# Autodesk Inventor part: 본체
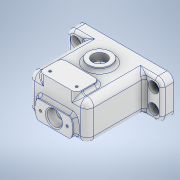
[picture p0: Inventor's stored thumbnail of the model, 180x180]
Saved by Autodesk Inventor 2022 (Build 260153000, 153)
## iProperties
Created: 2023-12
Part Number: 본체
Material: 알루미늄 6061
Document SubType Name: Modeling
Designer: PC-01
Density: 2.7 g/cm^3
Appearance: 알루미늄 - 평지
Mass: 225.061 g
Surface Area: 362.151 cm^2
Volume: 83.356 cm^3
Author: PC-01
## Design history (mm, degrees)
sketch "스케치1"
  geometry: L1 (-70, 0)-(70, 0) reference; L2 (0, -33.6)-(0, 33.6) reference; L3 (-50, 24)-(50, 24); L4 (50, 24)-(50, -24); L5 (50, -24)-(-50, -24); L6 (-50, -24)-(-50, 24); 1 further point
  constraints: 8 end point, 2 perpendicular, 1 horizontal, 2 other
  dimensions: "d0" = 100 distance of L3.start L3.end; "d1" = 48 distance of L3.end L4.end
extrude "돌출1" new body sketch "스케치1" stored distance "d2" = 76; taper "d3" = 0 deg
sketch "스케치2"
  geometry: L1 (50, -38)-(50, 38) reference; L2 (50, -26)-(31, -26); L3 (31, -26)-(31, 38); L4 (-50, 38)-(50, 38) reference; L5 (-31, 38)-(-31, -26); L6 (-31, -26)-(-50, -26); L7 (-50, -38)-(-50, 38) reference; L8 (31, 38)-(-31, 38); L9 (0, -53.2)-(0, 53.2) reference; L10 (70, 0)-(-70, 0) reference; L11 (50, -38)-(-50, -38) reference; L12 (50, -26)-(50, -38); L13 (50, -38)-(-50, -38); L14 (-50, -38)-(-50, -26); L15 (50, 38)-(50, -26); L16 (50, 38)-(31, 38); L17 (-31, 38)-(-50, 38); L18 (-50, 38)-(-50, -26); 2 further points
  constraints: 24 end point, 5 collinear, 5 perpendicular, 5 point on line, 1 vertical, 2 other
  dimensions: "d4" = 62 distance between parallel lines of L5 L3; "d5" = 12 distance between parallel lines of L11 L2
extrude "돌출2" cut sketch "스케치2" stored distance "d6" = 76; taper "d7" = 0 deg
sketch "스케치3"
  geometry: L1 (64, 0)-(0, 0) reference; L2 (76, 0)-(64, 0) reference; L3 (0, 0)-(76, 0); L4 (76, 0)-(76, 4); L5 (76, 48)-(76, 0) reference; L6 (0, 0)-(0, 48) reference; L7 (0, 0)-(0, 4); L8 (76, 4)-(0, 4); L9 (0, 48)-(64, 48) reference; L10 (0, 48)-(76, 48); L11 (76, 48)-(76, 44); L12 (76, 44)-(0, 44); L13 (0, 44)-(0, 48); 4 further points
  constraints: 16 end point, 3 point on line, 2 parallel, 2 perpendicular, 1 collinear, 1 horizontal
  dimensions: "d8" = 4 distance between parallel lines of L1 L8; "d9" = 4 distance between parallel lines of L9 L12
extrude "돌출3" cut sketch "스케치3" stored distance "d10" = 500; taper "d11" = 0 deg
sketch "스케치4" dims "d87" = 40
  geometry: L1 (19, -12)-(-81, -12) reference; L2 (19, 0)-(19, -12) reference; C1 r 20 at (-31, 16); 1 further point
  constraints: 1 centre point
  dimensions: "d12" = 40 diameter of C1; "d13" = 28 distance from line of L1 C1.centre; "d14" = 50 distance from line of L2 C1.centre
extrude "돌출4" join sketch "스케치4" distance "d15" = 4; taper "d16" = 0 deg
sketch "스케치5"
  geometry: L1 (64, 0)-(0, 0) reference; L2 (64, 40)-(0, 40) reference; L3 (0, 0)-(4, 0); L4 (4, 0)-(4, 40); L5 (4, 40)-(0, 40); L6 (0, 40)-(0, 0); 3 further points
  constraints: 8 end point, 2 parallel, 1 horizontal, 1 perpendicular, 1 point on line
  dimensions: "d17" = 4 distance between parallel lines of L6 L4
extrude "돌출5" cut sketch "스케치5" stored distance "d18" = 500; taper "d19" = 0 deg
sketch "스케치6"
  geometry: L1 (19, -72)-(81, -72) reference; L2 (70, -72)-(30, -72); L3 (30, -72)-(30, -48); L4 (30, -48)-(70, -48); L5 (70, -48)-(70, -72); L6 (19, -72)-(19, -12) reference; L7 (0, 0)-(100, 0) reference; L8 (100, 0)-(100, -12) reference; C1 r 12 at (50, -28); 2 further points
  constraints: 8 end point, 2 parallel, 1 centre point, 1 horizontal, 1 perpendicular, 1 point on line
  dimensions: "d20" = 24 distance of L4.end L2.start; "d21" = 40 distance of L3.end L4.end; "d22" = 11 distance between parallel lines of L6 L3; "d23" = 24 diameter of C1; "d24" = 28 distance from line of L7 C1.centre; "d25" = 50 distance from line of L8 C1.centre
extrude "돌출6" join sketch "스케치6" distance "d26" = 4; taper "d27" = 0 deg
sketch "스케치8"
  geometry: L1 (50, -28)-(-50, -28) reference; C1 r 9 at (0, 0); 1 further point
  constraints: 1 centre point
  dimensions: "d30" = 18 diameter of C1; "d31" = 28 distance from line of L1 C1.centre; "d32" = 10 distance of point (0, 10) C1.centre
extrude "돌출7" cut sketch "스케치8" distance "d33" = 8; taper "d34" = 0 deg
sketch "스케치10"
  geometry: C1 r 12 at (0, 0) reference; 2 further points
  constraints: 1 coincident
hole "구멍1" sketch "스케치10" at (0, 0) diameter "d35" = 14.91747; stored, may be unused: countersink angle "d39" = 90 deg, drill point angle "d41" = 0 deg; dims "d36" = 8, "d37" = 4, "d38" = 2, "d40" = 0.998
sketch "스케치12"
  geometry: L1 (27, -16)-(-27, -16); L2 (-27, -16)-(-27, 16); L3 (-27, 16)-(27, 16); L4 (27, 16)-(27, -16); L5 (70, 0)-(-70, 0) reference; L6 (0, -33.6)-(0, 33.6) reference; L7 (-50, -20)-(50, -20) reference; L8 (-31, -20)-(-31, 20) reference; 1 further point
  constraints: 8 end point, 2 parallel, 1 horizontal, 1 perpendicular, 2 other
  dimensions: "d42" = 4 distance between parallel lines of L1 L7; "d43" = 4 distance between parallel lines of L8 L2
extrude "돌출8" cut sketch "스케치12" distance "d44" = 66; taper "d45" = 0 deg
sketch "스케치13"
  geometry: L1 (50, -28)-(-50, -28) reference; L2 (50, -16)-(50, -28) reference; L3 (31, 44)-(31, -16) reference; L4 (-31, -16)-(-31, 44) reference; A1 r 15 centre (0, 0) between (0, 15) and (-15, 0); 3 further points
  constraints: 4 point on circle, 1 centre point
  dimensions: "d46" = 30 diameter of A1; "d47" = 28 distance from line of L1 A1.centre; "d48" = 50 distance from line of L2 A1.centre; "d49" = 31 distance from line of L3 A1.start; "d50" = 16 distance from line of L4 A1.end; "d51" = 16 distance from line of L3 point (15, 0); "d52" = 13 distance from line of L1 point (0, -15)
hole "구멍2" sketch "스케치13" at (0, 15), (-15, 0), (0, -15), (15, 0) diameter "d53" = 2.459; stored, may be unused: countersink angle "d57" = 90 deg, drill point angle "d59" = 0 deg; dims "d54" = 6, "d55" = 4, "d56" = 2, "d58" = 8.8
sketch "스케치14"
  geometry: L1 (30, -48)-(30, -72) reference; L2 (70, -72)-(70, -48) reference; L3 (30, -72)-(70, -72) reference; 3 further points
  dimensions: "d60" = 28 distance of point (36, -66) point (64, -66); "d61" = 6 distance from line of L1 point (36, -66); "d62" = 6 distance from line of L2 point (64, -66); "d63" = 6 distance from line of L3 point (64, -66)
hole "구멍3" sketch "스케치14" at (64, -66), (36, -66) diameter "d64" = 2.459; stored, may be unused: countersink angle "d68" = 90 deg, drill point angle "d70" = 0 deg; dims "d65" = 8, "d66" = 4, "d67" = 2, "d69" = 8
sketch "스케치15"
  geometry: L1 (100, 0)-(81, 0) reference; L2 (81, -40)-(100, -40) reference; L3 (100, 0)-(100, -40) reference; L4 (0, -40)-(0, 0) reference; 5 further points
  dimensions: "d71" = 20 distance of point (91, -10) point (91, -30); "d72" = 20 distance of point (9, -10) point (9, -30); "d73" = 82 distance of point (9, -30) point (91, -30); "d74" = 82 distance of point (9, -10) point (91, -10); "d75" = 10 distance from line of L1 point (91, -10); "d76" = 10 distance from line of L2 point (91, -30); "d77" = 9 distance from line of L3 point (91, -30); "d78" = 9 distance from line of L4 point (9, -30)
hole "구멍4" sketch "스케치15" at (91, -30), (91, -10), (9, -30), (9, -10) diameter "d79" = 6.756; stored, may be unused: countersink angle "d83" = 82 deg, drill point angle "d85" = 0 deg; dims "d80" = 8, "d81" = 11, "d82" = 6.6, "d84" = 12
sketch "스케치16"
  geometry: L1 (28, 44)-(4, 44) reference; L2 (-12, 0)-(-12, 40) reference; 2 further points
  constraints: 1 other
  dimensions: "d86" = 23 distance from line of L1 point (28, 21); "d87" = 40 distance from line of L2 point (28, 21)
feature "엠보싱1" sketch "스케치16" dims "d0" = 100, "d1" = 48, "d88" = 0.5, "d89" = 0
sketch "스케치17"
  geometry: L1 (-7.126, 23)-(-55.615, 23); L2 (-51, 44)-(-11, 44) reference; L3 (19, 40)-(19, 0) reference; L4 (0, 0)-(-62, 0) reference; L5 (-8.148, 3)-(-55.615, 3); L6 (-58, 36)-(-58, 4) reference; C1 r 20 at (-31, 13); 5 further points
  constraints: 4 end point, 1 centre point, 1 horizontal, 1 perpendicular
  dimensions: "d90" = 40 diameter of C1; "d91" = 31 distance from line of L2 C1.centre; "d92" = 50 distance from line of L3 C1.centre; "d95" = 10 distance from line of C1.centre L1; "d96" = 10 distance from line of L5 C1.centre
extrude "돌출9" join sketch "스케치17" distance "d97" = 4; taper "d98" = 0 deg
sketch "스케치18"
  geometry: L1 (-51, 44)-(-11, 44) reference; L2 (-81, 0)-(-81, 40) reference; C1 r 8 at (-31, 13); 1 further point
  constraints: 1 centre point
  dimensions: "d99" = 16 diameter of C1; "d100" = 31 distance from line of L1 C1.centre; "d101" = 50 distance from line of L2 C1.centre
extrude "돌출10" cut sketch "스케치18" distance "d102" = 20; taper "d103" = 0 deg
sketch "스케치19"
  geometry: L1 (19, 40)-(19, 0) reference; L2 (-81, 0)-(-81, 40) reference; L3 (-51, 44)-(-11, 44) reference; 3 further points
  dimensions: "d104" = 28 distance of point (-45, 13) point (-17, 13); "d105" = 36 distance from line of point (-17, 13) L1; "d106" = 36 distance from line of L2 point (-45, 13); "d107" = 31 distance from line of L3 point (-45, 13)
hole "구멍5" sketch "스케치19" at (-17, 13), (-45, 13) diameter "d108" = 2.459; stored, may be unused: countersink angle "d112" = 90 deg, drill point angle "d114" = 0 deg; dims "d109" = 10, "d110" = 4, "d111" = 2, "d113" = 8
fillet "모깎기1" dims "d115" = 7
fillet "모깎기2" dims "d116" = 7
chamfer "모따기1" distance "d117" = 1; stored, may be unused: second distance "d118" = 2, angle "d119" = 45 deg
fillet "모깎기3" dims "d120" = 5
fillet "모깎기4" dims "d121" = 7
fillet "모깎기5" dims "d122" = 3
fillet "모깎기6" dims "d123" = 3
fillet "모깎기7" dims "d124" = 3
sketch "스케치20"
  geometry: 1 further point
node "솔리드1"
feature "A9D066F2-1C7D-4E18-AEED-F7BC21143FA4" dims "d64" = 2.459, "d65" = 8, "d66" = 4, "d67" = 2, "d68" = 90 deg, "d69" = 8, "d70" = 0
